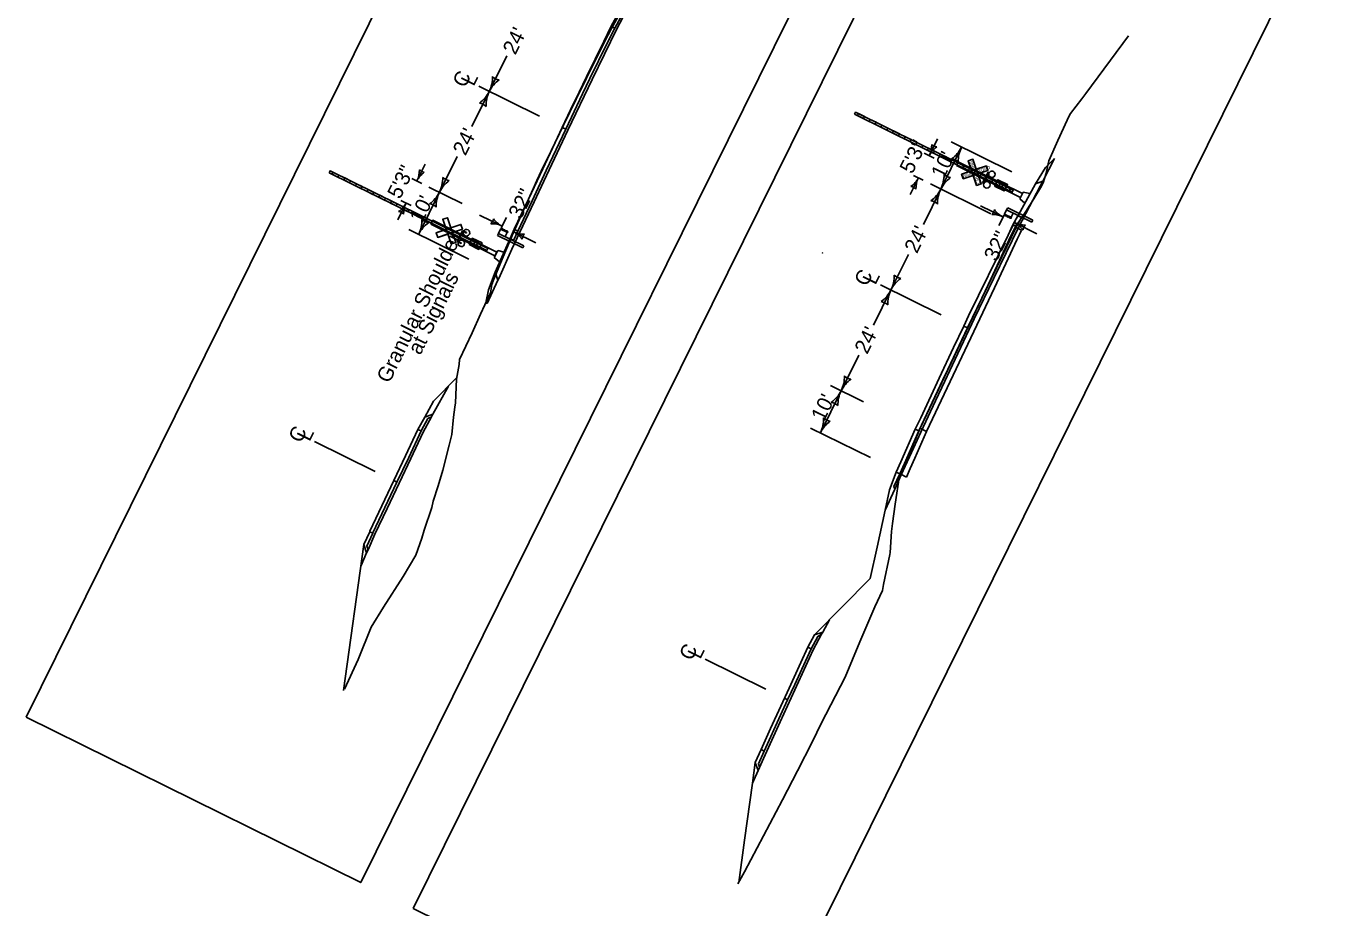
# Model space of a CAD drawing. Extents: x 14097936 to 14128734, y 8632000 to 8683104.
# Drawn here: x 14118892 to 14120004, y 8671718 to 8672470 of the extents above; entities that cross this region are included whole.
import ezdxf

# ---------------------------------------------------------------- set-up
doc = ezdxf.new("R2010")
doc.units = 0
for name, color, linetype in [('dsnCellElements', 7, 'Continuous'), ('dsnStdLineWork', 7, 'Continuous'), ('dsnTextOverlapEven', 7, 'Continuous'), ('TC_ExistingPavement', 7, 'Continuous'), ('TC_Grading', 7, 'Continuous'), ('TC_PCCPavement', 7, 'Continuous'), ('TC_ShoulderEarthFill', 7, 'Continuous'), ('TC_ShoulderGranular', 7, 'Continuous'), ('TC_Subbase', 7, 'Continuous'), ('Terrain', 7, 'Continuous')]:
    doc.layers.add(name, color=color, linetype=linetype)

# ---------------------------------------------------------------- blocks, each defined once
blk = doc.blocks.new('LT')
at = {"layer": 'dsnCellElements'}
for centre, radius, start, end in [((-3.56, 0), 1.64, 342.2666, 17.7333), ((0, 4.25), 4.25, 241.9275, 270), ((0, -4.25), 4.25, 90, 118.0725)]:
    blk.add_arc(centre, radius, start, end, dxfattribs=at)

msp = doc.modelspace()

# ---------------------------------------------------------------- linework, layer by layer
at = {"layer": 'dsnStdLineWork'}
for p, q in [((14119598.9, 8672395), (14119599.7, 8672396.7)), ((14119733.4, 8672328.6), (14119598.9, 8672395)), ((14119734.2, 8672330.2), (14119599.7, 8672396.7)), ((14119685.7, 8672351.1), (14119687.3, 8672354.4)), ((14119740.4, 8672324), (14119685.7, 8672351.1)), ((14119742.1, 8672327.4), (14119687.3, 8672354.4)), ((14119150.6, 8672345.1), (14119151.4, 8672346.8)), ((14119285.1, 8672278.6), (14119150.6, 8672345.1)), ((14119285.9, 8672280.3), (14119151.4, 8672346.8)), ((14119712.7, 8672345.6), (14119708.1, 8672336.3)), ((14119713, 8672345), (14119708.7, 8672336.5)), ((14119713.7, 8672345.2), (14119712.7, 8672345.6)), ((14119713.5, 8672344.7), (14119713, 8672345)), ((14119709.1, 8672335.8), (14119708.1, 8672336.3)), ((14119709.3, 8672336.2), (14119708.7, 8672336.5)), ((14119733.4, 8672328.6), (14119734.2, 8672330.2)), ((14119739.8, 8672322.8), (14119742.7, 8672328.6)), ((14119742.7, 8672328.6), (14119748.3, 8672327.4)), ((14119739.8, 8672322.8), (14119744.2, 8672319.1)), ((14119237.4, 8672301.2), (14119239, 8672304.5)), ((14119292.1, 8672274.1), (14119237.4, 8672301.2)), ((14119293.8, 8672277.4), (14119239, 8672304.5)), ((14119264.4, 8672295.7), (14119259.8, 8672286.3)), ((14119264.7, 8672295.1), (14119260.4, 8672286.5)), ((14119267.9, 8672294), (14119264.4, 8672295.7)), ((14119267.7, 8672293.6), (14119264.7, 8672295.1)), ((14119263.3, 8672284.6), (14119259.8, 8672286.3)), ((14119263.5, 8672285), (14119260.4, 8672286.5)), ((14119263.3, 8672284.6), (14119263.5, 8672285)), ((14119267.7, 8672293.6), (14119267.9, 8672294)), ((14119285.1, 8672278.6), (14119285.9, 8672280.3)), ((14119291.5, 8672272.8), (14119294.4, 8672278.7)), ((14119291.5, 8672272.8), (14119295.9, 8672269.1)), ((14119294.4, 8672278.7), (14119300, 8672277.4))]:
    msp.add_line(p, q, dxfattribs=at)
for points in [[(14119598.9, 8672395), (14119599.7, 8672396.7), (14119734.2, 8672330.2), (14119733.4, 8672328.6)], [(14119601.4, 8672393.8), (14119602.2, 8672395.5), (14119607.2, 8672393), (14119606.4, 8672391.4)], [(14119611.4, 8672388.9), (14119612.2, 8672390.5), (14119617.2, 8672388.1), (14119616.3, 8672386.4)], [(14119621.3, 8672384), (14119622.1, 8672385.6), (14119627.1, 8672383.2), (14119626.3, 8672381.5)], [(14119631.3, 8672379), (14119632.1, 8672380.7), (14119637.1, 8672378.2), (14119636.3, 8672376.6)], [(14119641.3, 8672374.1), (14119642.1, 8672375.8), (14119647.1, 8672373.3), (14119646.2, 8672371.7)], [(14119651.2, 8672369.2), (14119652, 8672370.8), (14119657, 8672368.4), (14119656.2, 8672366.7)], [(14119661.2, 8672364.3), (14119662, 8672365.9), (14119667, 8672363.5), (14119666.2, 8672361.8)], [(14119671.1, 8672359.3), (14119672, 8672361), (14119676.9, 8672358.5), (14119676.1, 8672356.9)], [(14119681.1, 8672354.4), (14119681.9, 8672356.1), (14119686.9, 8672353.6), (14119686.1, 8672352)], [(14119703, 8672334.2), (14119700.1, 8672342.8), (14119691.6, 8672339.9), (14119690.2, 8672343.8), (14119698.8, 8672346.7), (14119695.9, 8672355.3), (14119699.8, 8672356.6), (14119702.7, 8672348), (14119711.3, 8672350.9), (14119712.6, 8672347), (14119704.1, 8672344.1), (14119707, 8672335.5)], [(14119690.2, 8672343.8), (14119691.6, 8672339.9), (14119712.6, 8672347), (14119711.3, 8672350.9)], [(14119691.1, 8672349.5), (14119691.9, 8672351.2), (14119696.9, 8672348.7), (14119696, 8672347)], [(14119695.9, 8672355.3), (14119699.8, 8672356.6), (14119707, 8672335.5), (14119703, 8672334.2)], [(14119150.6, 8672345.1), (14119151.4, 8672346.8), (14119285.9, 8672280.3), (14119285.1, 8672278.6)], [(14119153.1, 8672343.9), (14119153.9, 8672345.5), (14119158.9, 8672343.1), (14119158.1, 8672341.4)], [(14119163.1, 8672338.9), (14119163.9, 8672340.6), (14119168.9, 8672338.1), (14119168.1, 8672336.5)], [(14119701, 8672344.6), (14119701.8, 8672346.2), (14119706.8, 8672343.8), (14119706, 8672342.1)], [(14119711, 8672339.6), (14119711.8, 8672341.3), (14119716.8, 8672338.8), (14119716, 8672337.2)], [(14119718.3, 8672333.6), (14119721, 8672339.1), (14119729.4, 8672335), (14119726.6, 8672329.5)], [(14119173, 8672334), (14119173.9, 8672335.7), (14119178.8, 8672333.2), (14119178, 8672331.6)], [(14119183, 8672329.1), (14119183.8, 8672330.8), (14119188.8, 8672328.3), (14119188, 8672326.6)], [(14119730.9, 8672329.8), (14119731.7, 8672331.5), (14119734.2, 8672330.2), (14119733.4, 8672328.6)], [(14119193, 8672324.2), (14119193.8, 8672325.8), (14119198.8, 8672323.4), (14119197.9, 8672321.7)], [(14119202.9, 8672319.2), (14119203.7, 8672320.9), (14119208.7, 8672318.4), (14119207.9, 8672316.8)], [(14119212.9, 8672314.3), (14119213.7, 8672316), (14119218.7, 8672313.5), (14119217.9, 8672311.9)], [(14119222.8, 8672309.4), (14119223.7, 8672311.1), (14119228.6, 8672308.6), (14119227.8, 8672306.9)], [(14119232.8, 8672304.5), (14119233.6, 8672306.1), (14119238.6, 8672303.7), (14119237.8, 8672302)], [(14119243.3, 8672289.9), (14119241.9, 8672293.9), (14119250.5, 8672296.8), (14119247.6, 8672305.3), (14119251.5, 8672306.6), (14119254.4, 8672298.1), (14119263, 8672301), (14119264.3, 8672297), (14119255.8, 8672294.1), (14119258.7, 8672285.6), (14119254.7, 8672284.3), (14119251.8, 8672292.8)], [(14119247.6, 8672305.3), (14119251.5, 8672306.6), (14119258.7, 8672285.6), (14119254.7, 8672284.3)], [(14119237.4, 8672301.2), (14119239, 8672304.5), (14119293.8, 8672277.4), (14119292.1, 8672274.1)], [(14119241.9, 8672293.9), (14119243.3, 8672289.9), (14119264.3, 8672297), (14119263, 8672301)], [(14119270, 8672283.7), (14119272.7, 8672289.2), (14119281.1, 8672285.1), (14119278.3, 8672279.6)], [(14119571.3, 8672276.6), (14119571.4, 8672276.7), (14119571.5, 8672276.6), (14119571.5, 8672276.5)]]:
    msp.add_lwpolyline(points, close=True, dxfattribs=at)
for centre, radius in [((14119716.1, 8672343.7), 2.78), ((14119716.1, 8672343.7), 2.78), ((14119711.7, 8672334.8), 2.78), ((14119711.7, 8672334.8), 2.78), ((14119723.8, 8672334.3), 1.39), ((14119275.5, 8672284.4), 1.39)]:
    msp.add_circle(centre, radius, dxfattribs=at)
for centre in [(14119267.8, 8672293.8), (14119263.4, 8672284.8)]:
    msp.add_arc(centre, 2.78, 158.4714, 148.911, dxfattribs=at)
at = {"layer": 'dsnTextOverlapEven'}
for p, q in [((14119287.2, 8672414.4), (14119302.2, 8672444.8)), ((14119330, 8672393.2), (14119278.3, 8672418.8)), ((14119272.4, 8672384.4), (14119287.2, 8672414.4)), ((14119662.6, 8672359.6), (14119669.7, 8672373.9)), ((14119666.8, 8672357.4), (14119658.3, 8672361.7)), ((14119672.4, 8672331), (14119690.2, 8672366.9)), ((14119733, 8672345.7), (14119681.2, 8672371.3)), ((14119225.5, 8672338.1), (14119232.6, 8672352.5)), ((14119244.7, 8672328.4), (14119259.7, 8672358.8)), ((14119229.8, 8672336), (14119221.2, 8672340.2)), ((14119646.2, 8672326.4), (14119653.3, 8672340.7)), ((14119657.5, 8672338.6), (14119649, 8672342.8)), ((14119227, 8672292.5), (14119244.7, 8672328.4)), ((14119264, 8672318.9), (14119235.7, 8672332.8)), ((14119657.6, 8672301), (14119672.4, 8672331)), ((14119715.2, 8672309.9), (14119663.5, 8672335.5)), ((14119209.1, 8672304.9), (14119216.2, 8672319.3)), ((14119220.5, 8672317.2), (14119211.9, 8672321.4)), ((14119725.6, 8672307.3), (14119706.4, 8672316.7)), ((14119298.2, 8672299.5), (14119279, 8672308.9)), ((14119297.4, 8672297.9), (14119301.8, 8672306.8)), ((14119726.4, 8672308.8), (14119722, 8672300)), ((14119728.6, 8672313.4), (14119726.8, 8672309.8)), ((14119726.8, 8672309.8), (14119732.8, 8672306.9)), ((14119728.6, 8672313.4), (14119729.5, 8672315.2)), ((14119728.6, 8672313.4), (14119750.1, 8672302.8)), ((14119729.5, 8672315.2), (14119751, 8672304.5)), ((14119734.3, 8672310.6), (14119732.5, 8672307)), ((14119269.8, 8672271.4), (14119218.7, 8672296.6)), ((14119295.2, 8672293.3), (14119296.9, 8672296.9)), ((14119296.9, 8672296.9), (14119302.9, 8672294)), ((14119300.8, 8672290.5), (14119302.6, 8672294.1)), ((14119307, 8672293.2), (14119311.4, 8672302)), ((14119327, 8672285.2), (14119307.8, 8672294.7)), ((14119736, 8672304.1), (14119731.6, 8672295.2)), ((14119754.3, 8672293), (14119735.2, 8672302.5)), ((14119750.1, 8672302.8), (14119751, 8672304.5)), ((14119295.2, 8672293.3), (14119294.3, 8672291.5)), ((14119294.3, 8672291.5), (14119315.8, 8672280.9)), ((14119295.2, 8672293.3), (14119316.7, 8672282.7)), ((14119316.7, 8672282.7), (14119315.8, 8672280.9)), ((14119629.9, 8672245), (14119644.9, 8672275.3)), ((14119615.1, 8672215), (14119629.9, 8672245)), ((14119672.7, 8672223.8), (14119620.9, 8672249.4)), ((14119587.4, 8672159), (14119602.4, 8672189.4)), ((14119606.6, 8672149.5), (14119578.4, 8672163.4)), ((14119569.7, 8672123.1), (14119587.4, 8672159)), ((14119612.4, 8672102), (14119561.4, 8672127.2)), ((14119190, 8672090.2), (14119138.2, 8672115.8)), ((14119523.3, 8671904.4), (14119471.5, 8671930))]:
    msp.add_line(p, q, dxfattribs=at)
for points in [[(14118892.1, 8671880.5), (14119388.5, 8672884.5), (14119674, 8672743.3), (14119177.6, 8671739.3)], [(14119222.4, 8671717.2), (14119718.8, 8672721.2), (14120004.4, 8672580), (14119508, 8671576)]]:
    msp.add_lwpolyline(points, close=True, dxfattribs=at)
for centre, major_axis, ratio, start_param, end_param in [((14119727.8, 8672309.3), (-0.48, -0.971), 0.951924, 4.712389, 7.853982), ((14119729.8, 8672308.3), (-1.14, 0.56), 0.852459, 0, 3.141593), ((14119731.9, 8672307.3), (-0.481, -0.973), 0.949899, 4.712389, 7.853982), ((14119297.9, 8672296.5), (-0.48, -0.971), 0.951924, 1.570796, 4.712389), ((14119299.9, 8672295.4), (-1.14, 0.56), 0.852459, 3.141593, 6.283185), ((14119302, 8672294.4), (-0.481, -0.973), 0.949899, 1.570796, 4.712389)]:
    msp.add_ellipse(centre, major_axis=major_axis, ratio=ratio, start_param=start_param, end_param=end_param, dxfattribs=at)
at = {"layer": 'TC_ExistingPavement'}
for p, q in [((14119736, 8672298.7), (14119741.4, 8672296)), ((14119654.9, 8672127), (14119660.3, 8672124.3)), ((14119637.7, 8672088), (14119643.1, 8672085.3))]:
    msp.add_line(p, q, dxfattribs=at)
msp.add_lwpolyline([(14119643.1, 8672085.3), (14119646.4, 8672092.7), (14119650.2, 8672101.5), (14119660.3, 8672124.3), (14119718.1, 8672246.9), (14119737.7, 8672288.4), (14119739.6, 8672292.3), (14119741.4, 8672296)], dxfattribs=at)
at = {"layer": 'TC_Grading'}
msp.add_line((14119564.8, 8671950.8), (14119612.3, 8671998.7), dxfattribs=at)
for points in [[(14119753.2, 8672335.7), (14119761.7, 8672349.4), (14119769.4, 8672357.1)], [(14119612.3, 8671998.7), (14119618.1, 8672025.5), (14119625, 8672057.1), (14119628.8, 8672074.6), (14119634.4, 8672089.6)], [(14119500, 8671739.4), (14119505, 8671775.5), (14119511.7, 8671824.1), (14119514.2, 8671841.9)]]:
    msp.add_lwpolyline(points, dxfattribs=at)
at = {"layer": 'TC_PCCPavement'}
for p, q in [((14119391.3, 8672470), (14119394.3, 8672468.5)), ((14119349.4, 8672383.6), (14119352.4, 8672382.2)), ((14119737, 8672299.1), (14119741.2, 8672306.8)), ((14119738.2, 8672308.3), (14119738.4, 8672308.6)), ((14119738.2, 8672308.3), (14119741.2, 8672306.8)), ((14119741.2, 8672306.8), (14119741.3, 8672307.1)), ((14119308.6, 8672296.8), (14119311.6, 8672295.3)), ((14119695.1, 8672212.8), (14119737, 8672299.1)), ((14119734, 8672300.6), (14119737, 8672299.1)), ((14119305, 8672288.8), (14119304.9, 8672288.5)), ((14119305, 8672288.8), (14119308, 8672287.3)), ((14119308, 8672287.3), (14119307.9, 8672287)), ((14119692.1, 8672214.2), (14119695.1, 8672212.8)), ((14119226.4, 8672126), (14119229.1, 8672124.7)), ((14119650.7, 8672126.2), (14119653.7, 8672124.7)), ((14119634.4, 8672089.6), (14119637.4, 8672088.2)), ((14119205.8, 8672082.4), (14119208.5, 8672081.1)), ((14119185.2, 8672038.7), (14119185.4, 8672039.1)), ((14119185.2, 8672038.7), (14119187.9, 8672037.4)), ((14119187.9, 8672037.4), (14119188, 8672037.7)), ((14119541.7, 8671895.2), (14119539.1, 8671896.6))]:
    msp.add_line(p, q, dxfattribs=at)
for points in [[(14119305, 8672288.8), (14119308.6, 8672296.8), (14119320.7, 8672322.6), (14119332.9, 8672348.4), (14119349.4, 8672383.7), (14119356.6, 8672398.8), (14119363.9, 8672413.9), (14119370.1, 8672427), (14119384.9, 8672457.1), (14119391.3, 8672470), (14119404.7, 8672494.6), (14119410.5, 8672505.2)], [(14119308, 8672287.3), (14119311.6, 8672295.3), (14119323.7, 8672321.1), (14119335.8, 8672347), (14119352.4, 8672382.2), (14119359.6, 8672397.3), (14119366.8, 8672412.5), (14119373.1, 8672425.5), (14119387.9, 8672455.6), (14119394.3, 8672468.5), (14119407.7, 8672493.1), (14119413.5, 8672503.7)], [(14119634.4, 8672089.6), (14119638.4, 8672098.5), (14119650.7, 8672126.2), (14119655.3, 8672136), (14119671.1, 8672169.7), (14119683.4, 8672195.8), (14119692.1, 8672214.2), (14119696.2, 8672222.9), (14119729.8, 8672291.9), (14119734, 8672300.6), (14119738.2, 8672308.3)], [(14119637.4, 8672088.2), (14119641.4, 8672097), (14119653.7, 8672124.7), (14119674.1, 8672168.2), (14119678.3, 8672177.1), (14119695.1, 8672212.8)], [(14119185.4, 8672039.1), (14119205.8, 8672082.4), (14119215.8, 8672103.5), (14119226.4, 8672126)], [(14119188, 8672037.7), (14119208.5, 8672081.1), (14119218.5, 8672102.1), (14119229.1, 8672124.7)], [(14119519.1, 8671852.9), (14119527.2, 8671870.7), (14119543.1, 8671905.3), (14119553, 8671927.1), (14119559, 8671940.2)], [(14119519.1, 8671852.9), (14119521.8, 8671851.6), (14119535.8, 8671882.3), (14119541.7, 8671895.2), (14119547.8, 8671908.4), (14119553.8, 8671921.5), (14119561.7, 8671938.9), (14119559, 8671940.2)]]:
    msp.add_lwpolyline(points, dxfattribs=at)
at = {"layer": 'TC_ShoulderEarthFill'}
for p, q in [((14119759.4, 8672337.8), (14119769.4, 8672357.1)), ((14119294.6, 8672253.4), (14119285.5, 8672233.5)), ((14119285.5, 8672233.5), (14119284.3, 8672234.1)), ((14119239.2, 8672139), (14119252.3, 8672162.9)), ((14119625, 8672057.1), (14119633.2, 8672075.1)), ((14119177.8, 8672009.8), (14119182.6, 8672020.7)), ((14119571.8, 8671953.1), (14119577.4, 8671963.5)), ((14119511.7, 8671824.1), (14119516.5, 8671834.9))]:
    msp.add_line(p, q, dxfattribs=at)
at = {"layer": 'TC_ShoulderGranular'}
for p, q in [((14119738.4, 8672308.6), (14119753.2, 8672335.7)), ((14119753.2, 8672335.7), (14119759.4, 8672337.8)), ((14119292.3, 8672260.2), (14119304.9, 8672288.5)), ((14119292.3, 8672260.2), (14119294.6, 8672253.4))]:
    msp.add_line(p, q, dxfattribs=at)
for points in [[(14119226.4, 8672126), (14119232.2, 8672136.6), (14119239.2, 8672139)], [(14119185.2, 8672038.7), (14119180.3, 8672027.7), (14119182.6, 8672020.7)], [(14119516.5, 8671834.9), (14119514.2, 8671841.9), (14119519.1, 8671852.9), (14119521.8, 8671851.6), (14119516.8, 8671840.6), (14119517.8, 8671837.7)]]:
    msp.add_lwpolyline(points, dxfattribs=at)
msp.add_lwpolyline([(14119559, 8671940.2), (14119564.8, 8671950.8), (14119571.8, 8671953.1), (14119570.7, 8671951.2), (14119567.5, 8671949.4), (14119561.7, 8671938.9)], close=True, dxfattribs=at)
at = {"layer": 'TC_Subbase'}
for p, q in [((14119738.8, 8672298.2), (14119757.2, 8672333.7)), ((14119238, 8672136.9), (14119239.2, 8672139)), ((14119182.6, 8672020.7), (14119183.8, 8672023.3))]:
    msp.add_line(p, q, dxfattribs=at)
for points in [[(14119294.6, 8672253.4), (14119295.3, 8672254.9), (14119306.6, 8672279.7), (14119313.4, 8672294.4), (14119325.5, 8672320.3), (14119333.8, 8672337.9), (14119354.2, 8672381.3), (14119374.9, 8672424.6), (14119396.1, 8672467.7), (14119414.5, 8672503.2), (14119420.5, 8672514.7)], [(14119757.2, 8672333.7), (14119758.3, 8672335.8), (14119759.4, 8672337.8)], [(14119633.2, 8672075.1), (14119638.7, 8672087.2), (14119649.2, 8672110.1), (14119655.5, 8672123.8), (14119668, 8672150.5), (14119675.9, 8672167.3), (14119680.1, 8672176.2), (14119696.3, 8672210.7), (14119698.9, 8672216.2), (14119701, 8672220.5), (14119717.8, 8672255), (14119738.8, 8672298.2)], [(14119183.8, 8672023.3), (14119189.7, 8672036.5), (14119200.1, 8672058.5), (14119210.3, 8672080.2), (14119220.3, 8672101.3), (14119230.9, 8672123.8), (14119238, 8672136.9)], [(14119229.1, 8672124.7), (14119234.9, 8672135.3), (14119238, 8672136.9)], [(14119637.4, 8672088.2), (14119632.5, 8672077.2), (14119633.2, 8672075.1)], [(14119183.8, 8672023.3), (14119182.8, 8672026.5), (14119187.9, 8672037.4)], [(14119516.5, 8671834.9), (14119521.2, 8671845.3), (14119535.4, 8671876.6), (14119563.5, 8671938), (14119570.7, 8671951.2)]]:
    msp.add_lwpolyline(points, dxfattribs=at)
at = {"layer": 'Terrain'}
msp.add_line((14119180.3, 8672027.7), (14119162.9, 8671903.1), dxfattribs=at)
for points in [[(14119163.6, 8671904.4), (14119175.5, 8671929.7), (14119186.5, 8671957.2), (14119197, 8671974.4), (14119213.9, 8672000.6), (14119224.6, 8672018.6), (14119229.6, 8672033.1), (14119231.8, 8672040.1), (14119238.1, 8672059.5), (14119239.3, 8672064.7), (14119243.5, 8672078), (14119247.5, 8672091.3), (14119252.9, 8672112.5), (14119255.3, 8672121.6), (14119256.8, 8672136.6), (14119257.9, 8672144.9), (14119258.4, 8672148.8), (14119259.3, 8672168.8), (14119260.5, 8672175.1), (14119261.6, 8672181.4), (14119261.9, 8672185.6), (14119267.2, 8672197), (14119272.6, 8672208.4), (14119279.8, 8672224.3), (14119287, 8672240.3), (14119288.4, 8672242.5), (14119289.2, 8672247.6), (14119289.4, 8672249.9), (14119289.9, 8672250.8), (14119290, 8672251.5), (14119290.6, 8672252.8), (14119299, 8672273.2), (14119307.5, 8672293.6), (14119308.2, 8672294.7), (14119316.4, 8672313), (14119324.7, 8672331.3), (14119327.9, 8672338.5), (14119331.6, 8672346.3), (14119339.9, 8672363.6), (14119350.5, 8672385.6), (14119361.4, 8672407.9), (14119379.4, 8672444.1), (14119388.7, 8672462.7), (14119391.6, 8672468.2), (14119401.4, 8672486)], [(14119499.4, 8671738.3), (14119504.9, 8671748.4), (14119521.2, 8671779.1), (14119537.4, 8671809.9), (14119550.1, 8671834.8), (14119562.9, 8671859.6), (14119570.5, 8671875.1), (14119590.7, 8671914.7), (14119603.4, 8671944.7), (14119616.1, 8671974.6), (14119622.6, 8671988.5), (14119623.6, 8671993.6), (14119628.9, 8672019.3), (14119629.1, 8672020.9), (14119630.5, 8672038.9), (14119631.2, 8672045.8), (14119633.5, 8672062.1), (14119637.1, 8672086.6), (14119641, 8672095.4), (14119644.9, 8672104.1), (14119649.9, 8672115.6), (14119654.9, 8672127), (14119683.8, 8672188.3), (14119712.8, 8672249.5), (14119722.5, 8672270.3), (14119732.3, 8672291.1), (14119734.2, 8672295), (14119736, 8672298.7), (14119736.9, 8672300.5), (14119739.7, 8672303.9), (14119743.3, 8672309.4), (14119745, 8672312), (14119751.7, 8672322.8), (14119758.4, 8672333.7), (14119759.8, 8672336.5), (14119762.4, 8672344.8), (14119763.4, 8672350), (14119764.5, 8672355.2), (14119772.4, 8672372.6), (14119780.3, 8672390), (14119782.5, 8672394.7), (14119783.2, 8672395.5), (14119792.7, 8672408.2), (14119796.2, 8672412.8), (14119832.6, 8672461.9)], [(14119284.3, 8672234.1), (14119286.7, 8672245.2), (14119292.3, 8672260.2)], [(14119232.2, 8672136.6), (14119239.6, 8672150.1), (14119259.6, 8672170.4)]]:
    msp.add_lwpolyline(points, dxfattribs=at)

# ---------------------------------------------------------------- block references
at = {"layer": 'dsnTextOverlapEven'}
for p, xscale, yscale, rotation in [((14119287.2, 8672414.4), 6.308076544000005, 6.308076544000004, -116.30889254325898), ((14119287.2, 8672414.4), 6.308076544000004, 6.308076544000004, 63.69110745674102), ((14119662.6, 8672359.6), 4.731057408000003, 4.731057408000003, -116.30889254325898), ((14119690.1, 8672366.8), 6.308076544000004, 6.308076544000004, 63.69110745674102), ((14119225.5, 8672338.1), 4.731057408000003, 4.731057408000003, -116.30889254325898), ((14119244.7, 8672328.4), 6.308076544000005, 6.308076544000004, -116.30889254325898), ((14119653.3, 8672340.7), 4.7310574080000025, 4.7310574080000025, 63.69110745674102), ((14119672.4, 8672331), 6.308076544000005, 6.308076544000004, -116.30889254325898), ((14119244.7, 8672328.4), 6.308076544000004, 6.308076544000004, 63.69110745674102), ((14119672.4, 8672331), 6.308076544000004, 6.308076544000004, 63.69110745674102), ((14119216.2, 8672319.3), 4.7310574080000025, 4.7310574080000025, 63.69110745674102), ((14119227, 8672292.5), 6.308076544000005, 6.308076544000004, -116.30889254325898), ((14119298.2, 8672299.5), 4.7310574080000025, -4.731057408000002, -26.30877033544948), ((14119725.6, 8672307.3), 4.7310574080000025, 4.731057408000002, -26.30889254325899), ((14119307.8, 8672294.7), 4.7310574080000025, -4.731057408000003, 153.69122966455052), ((14119735.2, 8672302.5), 4.7310574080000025, 4.7310574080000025, 153.691107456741), ((14119629.9, 8672245), 6.308076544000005, 6.308076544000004, -116.30889254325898), ((14119629.9, 8672245), 6.308076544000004, 6.308076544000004, 63.69110745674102), ((14119587.4, 8672159), 6.308076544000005, 6.308076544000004, -116.30889254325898), ((14119587.4, 8672159), 6.308076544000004, 6.308076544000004, 63.69110745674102), ((14119569.7, 8672123.1), 6.308076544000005, 6.308076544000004, -116.30889254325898)]:
    msp.add_blockref('LT', p, dxfattribs=dict(at, xscale=xscale, yscale=yscale, rotation=rotation))

# ---------------------------------------------------------------- texts
at = {"layer": 'dsnStdLineWork'}
for s, rotation, p in [('CROSSING', 108.6912, (14119706, 8672336.1)), ('ROAD', 18.6912, (14119704.3, 8672344.9)), ('RAIL', 18.6912, (14119691.8, 8672340.7))]:
    msp.add_text(s, height=2.78, rotation=rotation, dxfattribs=at).set_placement(p)
at = {"layer": 'dsnTextOverlapEven'}
for s, rotation, p in [("24'", 63.6911, (14119309.5, 8672444.9)), ('C', 63.6911, (14119266.7, 8672416.8)), ('L', 63.6911, (14119273.9, 8672418.2)), ("24'", 63.6911, (14119266.9, 8672358.9)), ('5\'3"', 63.6911, (14119648.1, 8672343.3)), ("10'", 63.6911, (14119674.9, 8672339)), ('5\'3"', 63.6911, (14119211.1, 8672321.8)), ('32"', 63.6912, (14119314.3, 8672304.7)), ("10'", 63.6911, (14119229.9, 8672301.4)), ('Granular Shoulder', 63.6912, (14119201.9, 8672164.7)), ("24'", 63.6911, (14119652.1, 8672275.5)), ('32"', 63.6911, (14119720, 8672268.6)), ('C', 63.6911, (14119609.4, 8672247.3)), ('at Signals', 63.6912, (14119228.4, 8672188.8)), ('L', 63.6911, (14119616.6, 8672248.7)), ("24'", 63.6911, (14119609.6, 8672189.5)), ("10'", 63.6911, (14119572.6, 8672132)), ('C', 63.6911, (14119126.7, 8672113.7)), ('L', 63.6911, (14119133.9, 8672115.1)), ('C', 63.6911, (14119460, 8671927.9)), ('L', 63.6911, (14119467.2, 8671929.3))]:
    msp.add_text(s, height=12.8, rotation=rotation, dxfattribs=at).set_placement(p)

doc.saveas('drawing.dxf')
